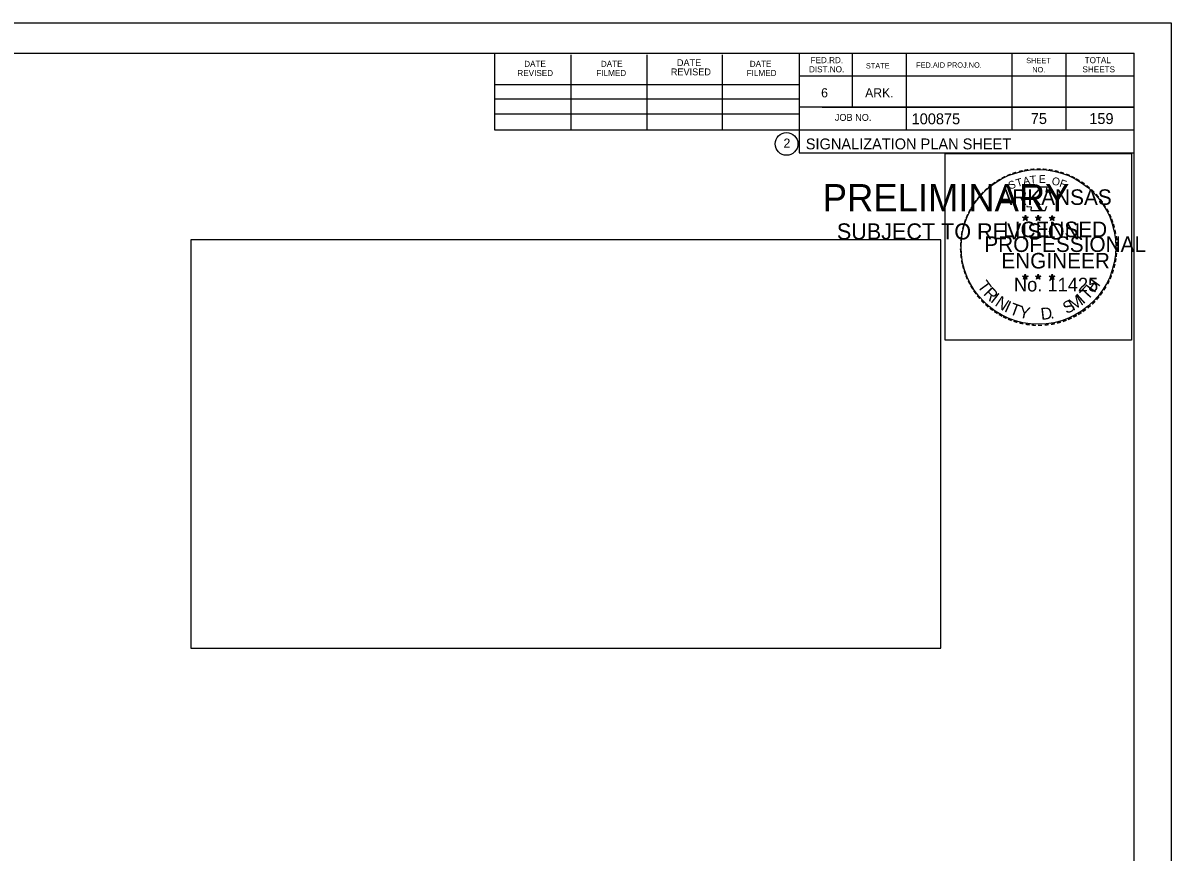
# Model space of a CAD drawing. Extents: x 1710114 to 1711114, y 557211 to 557851.
# Drawn here: x 1710671.2 to 1711114.3, y 557531.1 to 557851.1 of the extents above; entities that cross this region are included whole.
import ezdxf

# ---------------------------------------------------------------- set-up
doc = ezdxf.new("R2010")
doc.units = 0
for name, color, linetype in [('E_Existing ROW', 7, 'Continuous'), ('R_Alt Surface', 7, 'Continuous'), ('R_Alt Surface Annot', 7, 'Continuous'), ('R_Axis', 7, 'Continuous'), ('R_Axis Annot', 7, 'Continuous')]:
    doc.layers.add(name, color=color, linetype=linetype)

msp = doc.modelspace()

# ---------------------------------------------------------------- linework, layer by layer
at = {"layer": 'E_Existing ROW'}
msp.add_lwpolyline([(1710735.98, 557609.87), (1711025.48, 557609.87), (1711025.48, 557767.42), (1710735.98, 557767.42)], close=True, dxfattribs=at)
at = {"layer": 'R_Alt Surface'}
for p, q in [((1710151.54, 557839.47), (1711100.08, 557839.47)), ((1710853.3, 557809.83), (1710853.3, 557839.47)), ((1710882.88, 557809.83), (1710882.88, 557838.87)), ((1710912.16, 557809.83), (1710912.16, 557838.87)), ((1710941.2, 557809.83), (1710941.2, 557838.87)), ((1710970.78, 557839.47), (1710970.78, 557801.07)), ((1710991.3, 557839.47), (1710991.3, 557818.65)), ((1711012.12, 557839.47), (1711012.12, 557809.83)), ((1711052.86, 557839.47), (1711052.86, 557809.83)), ((1711073.68, 557839.47), (1711073.68, 557809.83)), ((1711100.08, 557223.09), (1711100.08, 557839.47)), ((1711100.08, 557830.65), (1710970.78, 557830.65)), ((1711100.08, 557830.71), (1711100.08, 557830.71)), ((1710853.3, 557827.41), (1710970.78, 557827.41)), ((1710853.3, 557821.83), (1710970.78, 557821.83)), ((1710853.3, 557809.83), (1710853.3, 557816.01)), ((1710853.3, 557816.01), (1710970.78, 557816.01)), ((1711100.08, 557818.65), (1710970.78, 557818.65)), ((1710979.66, 557818.65), (1711100.08, 557818.65)), ((1711100.08, 557809.83), (1710853.3, 557809.83)), ((1710970.78, 557801.07), (1711100.08, 557801.07))]:
    msp.add_line(p, q, dxfattribs=at)
msp.add_circle((1710965.94, 557804.47), 4.4, dxfattribs=at)
at = {"layer": 'R_Alt Surface Annot'}
for p, q in [((1710114.34, 557851.15), (1711114.34, 557851.15)), ((1711026.91, 557732.02), (1711026.91, 557732.02))]:
    msp.add_line(p, q, dxfattribs=at)
for points in [[(1710114.32, 557851.15), (1711114.34, 557851.15), (1711114.34, 557211.14), (1710114.32, 557211.14)], [(1711027.14, 557800.7), (1711099.14, 557800.7), (1711099.14, 557728.7), (1711027.14, 557728.7)]]:
    msp.add_lwpolyline(points, close=True, dxfattribs=at)
msp.add_circle((1711063.14, 557764.7), 29.86, dxfattribs=at)
at = {"layer": 'R_Axis Annot'}
for p, q in [((1711057.06, 557776.15), (1711058.11, 557775.81)), ((1711057.06, 557776.15), (1711057.82, 557776.01)), ((1711057.06, 557776.15), (1711057.77, 557775.78)), ((1711057.46, 557774.92), (1711058.11, 557775.81)), ((1711057.46, 557774.92), (1711057.84, 557775.66)), ((1711057.46, 557774.92), (1711058.1, 557775.57)), ((1711058.11, 557776.91), (1711057.99, 557776.15)), ((1711058.75, 557774.92), (1711058.1, 557775.57)), ((1711058.11, 557775.81), (1711058.11, 557776.91)), ((1711058.11, 557776.91), (1711058.26, 557776.16)), ((1711059.15, 557776.15), (1711058.11, 557775.81)), ((1711058.75, 557774.92), (1711058.11, 557775.81)), ((1711059.15, 557776.15), (1711058.29, 557776)), ((1711058.75, 557774.92), (1711058.34, 557775.8)), ((1711059.15, 557776.15), (1711058.54, 557775.84)), ((1711062.07, 557776.15), (1711063.12, 557775.81)), ((1711062.07, 557776.15), (1711062.83, 557776.01)), ((1711062.07, 557776.15), (1711062.78, 557775.78)), ((1711062.47, 557774.92), (1711063.12, 557775.81)), ((1711062.47, 557774.92), (1711062.85, 557775.66)), ((1711062.47, 557774.92), (1711063.11, 557775.57)), ((1711063.12, 557776.91), (1711063, 557776.15)), ((1711063.76, 557774.92), (1711063.11, 557775.57)), ((1711063.12, 557775.81), (1711063.12, 557776.91)), ((1711063.12, 557776.91), (1711063.27, 557776.16)), ((1711064.16, 557776.15), (1711063.12, 557775.81)), ((1711063.76, 557774.92), (1711063.12, 557775.81)), ((1711064.16, 557776.15), (1711063.3, 557776)), ((1711063.76, 557774.92), (1711063.35, 557775.8)), ((1711064.16, 557776.15), (1711063.55, 557775.84)), ((1711067.36, 557776.11), (1711068.41, 557775.78)), ((1711067.36, 557776.11), (1711068.12, 557775.98)), ((1711067.36, 557776.11), (1711068.08, 557775.75)), ((1711067.76, 557774.89), (1711068.41, 557775.78)), ((1711067.76, 557774.89), (1711068.14, 557775.62)), ((1711067.76, 557774.89), (1711068.41, 557775.54)), ((1711068.41, 557776.87), (1711068.29, 557776.12)), ((1711068.41, 557775.78), (1711068.41, 557776.87)), ((1711068.41, 557776.87), (1711068.56, 557776.12)), ((1711069.45, 557776.11), (1711068.41, 557775.78)), ((1711069.05, 557774.89), (1711068.41, 557775.78)), ((1711069.05, 557774.89), (1711068.41, 557775.53)), ((1711069.45, 557776.11), (1711068.59, 557775.96)), ((1711069.05, 557774.89), (1711068.64, 557775.76)), ((1711069.45, 557776.11), (1711068.84, 557775.81)), ((1711057.05, 557753.43), (1711058.1, 557753.1)), ((1711057.05, 557753.43), (1711057.81, 557753.29)), ((1711057.05, 557753.43), (1711057.76, 557753.06)), ((1711057.45, 557752.2), (1711058.1, 557753.1)), ((1711057.45, 557752.2), (1711057.83, 557752.94)), ((1711058.1, 557754.19), (1711057.97, 557753.43)), ((1711058.1, 557753.1), (1711058.1, 557754.19)), ((1711058.1, 557754.19), (1711058.24, 557753.44)), ((1711059.14, 557753.43), (1711058.1, 557753.1)), ((1711058.74, 557752.2), (1711058.1, 557753.1)), ((1711059.14, 557753.43), (1711058.28, 557753.28)), ((1711058.74, 557752.2), (1711058.33, 557753.08)), ((1711059.14, 557753.43), (1711058.53, 557753.12)), ((1711062.06, 557753.43), (1711063.1, 557753.1)), ((1711062.06, 557753.43), (1711062.82, 557753.29)), ((1711062.06, 557753.43), (1711062.77, 557753.06)), ((1711062.46, 557752.2), (1711063.1, 557753.1)), ((1711062.46, 557752.2), (1711062.83, 557752.94)), ((1711063.1, 557754.19), (1711062.98, 557753.43)), ((1711063.1, 557753.1), (1711063.1, 557754.19)), ((1711063.1, 557754.19), (1711063.25, 557753.44)), ((1711064.15, 557753.43), (1711063.1, 557753.1)), ((1711063.74, 557752.2), (1711063.1, 557753.1)), ((1711064.15, 557753.43), (1711063.29, 557753.28)), ((1711063.74, 557752.2), (1711063.33, 557753.08)), ((1711064.15, 557753.43), (1711063.53, 557753.12)), ((1711067.36, 557753.4), (1711068.41, 557753.07)), ((1711067.36, 557753.4), (1711068.12, 557753.26)), ((1711067.36, 557753.4), (1711068.07, 557753.03)), ((1711067.76, 557752.17), (1711068.41, 557753.07)), ((1711067.76, 557752.17), (1711068.14, 557752.91)), ((1711068.41, 557754.16), (1711068.28, 557753.4)), ((1711068.41, 557753.07), (1711068.41, 557754.16)), ((1711068.41, 557754.16), (1711068.55, 557753.41)), ((1711069.45, 557753.4), (1711068.41, 557753.07)), ((1711069.04, 557752.17), (1711068.41, 557753.07)), ((1711069.45, 557753.4), (1711068.59, 557753.25)), ((1711069.04, 557752.17), (1711068.63, 557753.05)), ((1711069.45, 557753.4), (1711068.83, 557753.09)), ((1711057.45, 557752.2), (1711058.09, 557752.86)), ((1711058.74, 557752.2), (1711058.09, 557752.85)), ((1711062.46, 557752.2), (1711063.1, 557752.86)), ((1711063.74, 557752.2), (1711063.1, 557752.85)), ((1711067.76, 557752.17), (1711068.4, 557752.83)), ((1711069.04, 557752.17), (1711068.4, 557752.82))]:
    msp.add_line(p, q, dxfattribs=at)
for points in [[(1711057.19, 557787.78), (1711057.99, 557785.3)], [(1711067.72, 557785.02), (1711068.14, 557785.87), (1711066.09, 557785.8), (1711066.53, 557787.78), (1711057.19, 557787.78)], [(1711058.66, 557780.51), (1711058.66, 557780.25), (1711060.35, 557780.19), (1711060.19, 557778.78), (1711065.8, 557778.78), (1711066.4, 557780.38)], [(1711058.11, 557776.91), (1711058.75, 557774.92), (1711057.06, 557776.15), (1711059.15, 557776.15), (1711057.46, 557774.92), (1711058.11, 557776.91)], [(1711063.12, 557776.91), (1711063.76, 557774.92), (1711062.07, 557776.15), (1711064.16, 557776.15), (1711062.47, 557774.92), (1711063.12, 557776.91)], [(1711068.41, 557776.87), (1711069.05, 557774.89), (1711067.36, 557776.11), (1711069.45, 557776.11), (1711067.76, 557774.89), (1711068.41, 557776.87)], [(1711058.1, 557754.19), (1711058.74, 557752.2), (1711057.05, 557753.43), (1711059.14, 557753.43), (1711057.45, 557752.2), (1711058.1, 557754.19)], [(1711063.1, 557754.19), (1711063.74, 557752.2), (1711062.06, 557753.43), (1711064.15, 557753.43), (1711062.46, 557752.2), (1711063.1, 557754.19)], [(1711068.41, 557754.16), (1711069.04, 557752.17), (1711067.36, 557753.4), (1711069.45, 557753.4), (1711067.76, 557752.17), (1711068.41, 557754.16)]]:
    msp.add_lwpolyline(points, dxfattribs=at)
for centre, radius in [((1711058.11, 557775.81), 0.517), ((1711058.11, 557775.81), 0.434), ((1711058.11, 557775.81), 0.347), ((1711058.11, 557775.81), 0.297), ((1711058.11, 557775.81), 0.224), ((1711058.11, 557775.81), 0.149), ((1711058.11, 557775.81), 0.0889), ((1711063.12, 557775.81), 0.517), ((1711063.12, 557775.81), 0.434), ((1711063.12, 557775.81), 0.347), ((1711063.12, 557775.81), 0.297), ((1711063.12, 557775.81), 0.224), ((1711063.12, 557775.81), 0.149), ((1711063.12, 557775.81), 0.0889), ((1711068.41, 557775.78), 0.517), ((1711068.41, 557775.78), 0.434), ((1711068.41, 557775.78), 0.347), ((1711068.41, 557775.78), 0.297), ((1711068.41, 557775.78), 0.224), ((1711068.41, 557775.78), 0.149), ((1711068.41, 557775.78), 0.0889), ((1711058.09, 557753.09), 0.517), ((1711058.09, 557753.09), 0.434), ((1711058.09, 557753.09), 0.347), ((1711058.09, 557753.09), 0.297), ((1711058.09, 557753.09), 0.224), ((1711058.09, 557753.09), 0.149), ((1711058.09, 557753.09), 0.0889), ((1711063.1, 557753.09), 0.517), ((1711063.1, 557753.09), 0.434), ((1711063.1, 557753.09), 0.347), ((1711063.1, 557753.09), 0.297), ((1711063.1, 557753.09), 0.224), ((1711063.1, 557753.09), 0.149), ((1711063.1, 557753.09), 0.0889), ((1711068.4, 557753.06), 0.517), ((1711068.4, 557753.06), 0.434), ((1711068.4, 557753.06), 0.347), ((1711068.4, 557753.06), 0.297), ((1711068.4, 557753.06), 0.224), ((1711068.4, 557753.06), 0.149), ((1711068.4, 557753.06), 0.0889)]:
    msp.add_circle(centre, radius, dxfattribs=at)

# ---------------------------------------------------------------- texts
at = {"layer": 'R_Alt Surface'}
for s, height, p in [('DATE', 2.638, (1710923.62, 557834.49)), ('FED.RD.', 2.346, (1710975.22, 557835.63)), ('SHEET', 2.052, (1711058.44, 557835.63)), ('TOTAL', 2.346, (1711081, 557835.63)), ('REVISED', 2.346, (1710862.06, 557830.65)), ('DATE', 2.346, (1710864.7, 557834.19)), ('FILMED', 2.346, (1710892.54, 557830.65)), ('DATE', 2.346, (1710894.28, 557834.19)), ('REVISED', 2.638, (1710921.28, 557830.95)), ('FILMED', 2.346, (1710950.56, 557830.65)), ('DATE', 2.346, (1710951.76, 557834.19)), ('DIST.NO.', 2.346, (1710974.62, 557832.09)), ('STATE', 2.052, (1710996.58, 557833.59)), ('FED.AID PROJ.NO.', 2.052, (1711015.96, 557833.89)), ('NO.', 2.052, (1711060.78, 557832.09)), ('SHEETS', 2.346, (1711080.16, 557832.09)), ('6', 3.52, (1710979.3, 557822.43)), ('ARK.', 3.517, (1710996.28, 557822.43)), ('JOB NO.', 2.638, (1710984.58, 557813.37)), ('100875', 4.2, (1711014.21, 557812.04)), ('75', 4.2, (1711060.2, 557812.14)), ('159', 4.2, (1711082.78, 557812.14)), ('2', 3.52, (1710964.79, 557803.01)), ('SIGNALIZATION PLAN SHEET', 4.2, (1710973.37, 557802.36))]:
    msp.add_text(s, height=height, dxfattribs=at).set_placement(p)
at = {"layer": 'R_Axis'}
for s, height, p in [('PRELIMINARY', 10.5, (1710979.93, 557778.46)), ('SUBJECT TO REVISION', 6.2253, (1710985.36, 557767.57))]:
    msp.add_text(s, height=height, dxfattribs=at).set_placement(p)
at = {"layer": 'R_Axis Annot'}
for s, height, rotation, p in [('-', 4.8, 24.3072, (1711051.53, 557790.36)), ('-', 4.8, 19.1761, (1711053.43, 557791.16)), ('-', 4.8, 13.6302, (1711055.68, 557791.89)), ('-', 4.8, 10.2193, (1711057.71, 557792.37)), ('-', 4.8, 5.8968, (1711059.9, 557792.7)), ('-', 4.8, 0.1862, (1711062.22, 557792.92)), ('-', 4.8, 357.743, (1711064.39, 557792.88)), ('-', 4.8, 352.1617, (1711066.62, 557792.71)), ('-', 4.8, 347.2049, (1711068.77, 557792.37)), ('-', 4.8, 342.3362, (1711070.68, 557791.9)), ('-', 4.8, 337.8551, (1711072.88, 557791.23)), ('-', 4.8, 38.9507, (1711044.68, 557785.98)), ('-', 4.8, 36.2317, (1711046.1, 557787.11)), ('-', 4.8, 34.0636, (1711047.84, 557788.29)), ('-', 4.8, 28.7918, (1711049.63, 557789.4)), ('S', 3, 21.594, (1711052.25, 557786.82)), ('T', 3, 16.4036, (1711054.99, 557787.81)), ('A', 3, 11.2132, (1711057.47, 557788.56)), ('T', 3, 6.0228, (1711060.02, 557789.06)), ('E', 3, 0.8323, (1711063.33, 557789.39)), ('O', 3, 350.4515, (1711068.14, 557788.76)), ('F', 3, 340.0707, (1711071.01, 557788.08)), ('-', 4.8, 334.1211, (1711074.78, 557790.42)), ('-', 4.8, 329.6409, (1711076.51, 557789.57)), ('-', 4.8, 325.8627, (1711078.44, 557788.49)), ('-', 4.8, 320.5297, (1711080.27, 557787.21)), ('-', 4.8, 50.6142, (1711040.82, 557781.83)), ('-', 4.8, 48.4231, (1711042.03, 557783.29)), ('-', 4.8, 42.9622, (1711043.38, 557784.72)), ('-', 4.8, 315.5786, (1711082.07, 557785.75)), ('-', 4.8, 309.8797, (1711083.78, 557784.1)), ('-', 4.8, 58.0706, (1711038.61, 557778.55)), ('-', 4.8, 54.2325, (1711039.58, 557780.13)), ('-', 4.8, 306.6522, (1711085.35, 557782.29)), ('-', 4.2, 303.6753, (1711086.81, 557780.59)), ('-', 4.8, 299.6684, (1711087.77, 557778.77)), ('-', 4.8, 72.3945, (1711036.24, 557772.99)), ('-', 4.8, 67.7743, (1711036.89, 557774.88)), ('-', 4.8, 62.8713, (1711037.67, 557776.71)), ('-', 4.8, 294.6628, (1711088.74, 557776.93)), ('-', 4.8, 290.5728, (1711089.51, 557775.2)), ('-', 4.8, 81.2013, (1711035.25, 557768.7)), ('-', 4.8, 75.461, (1711035.65, 557770.84)), ('-', 4.8, 285.1233, (1711090.21, 557773.46)), ('-', 4.8, 280.5493, (1711090.81, 557771.23)), ('-', 4.8, 89.0622, (1711034.95, 557764.53)), ('-', 4.8, 85.1863, (1711035.02, 557766.63)), ('-', 4.8, 276.5962, (1711091.3, 557768.93)), ('-', 4.8, 274.3301, (1711091.48, 557766.76)), ('-', 4.8, 94.1959, (1711035.05, 557762.35)), ('-', 4.8, 98.9479, (1711035.27, 557760.35)), ('-', 4.8, 263.5172, (1711091.52, 557762.87)), ('-', 4.8, 269.9407, (1711091.58, 557764.87)), ('-', 4.8, 101.7149, (1711035.67, 557758.15)), ('-', 4.8, 105.4578, (1711036.16, 557756.37)), ('-', 4.8, 255.7626, (1711090.98, 557758.87)), ('-', 4.8, 260.9953, (1711091.31, 557760.91)), ('-', 4.8, 109.0874, (1711036.8, 557754.48)), ('-', 4.8, 114.0643, (1711037.57, 557752.69)), ('-', 4.8, 247.8887, (1711089.77, 557754.69)), ('-', 4.8, 252.8681, (1711090.44, 557756.71)), ('-', 4.8, 115.7289, (1711038.48, 557750.83)), ('-', 4.8, 120.4471, (1711039.55, 557749.08)), ('T', 4.62, 306.0406, (1711039.38, 557749.61)), ('R', 4.62, 314.005, (1711041.66, 557746.47)), ('T', 4.62, 46.6444, (1711082.07, 557743.89)), ('H', 4.62, 54.6088, (1711084.74, 557746.72)), ('-', 4.8, 239.0712, (1711087.8, 557750.55)), ('-', 4.8, 244.6197, (1711088.98, 557752.81)), ('-', 4.8, 125.8934, (1711040.76, 557747.39)), ('-', 4.8, 130.7181, (1711042.15, 557745.74)), ('-', 4.8, 134.2238, (1711043.7, 557744.1)), ('I', 4.62, 321.9694, (1711044.37, 557743.67)), ('N', 4.62, 326.5002, (1711046.07, 557742.26)), ('S', 4.62, 26.9312, (1711074.01, 557738.7)), ('M', 4.62, 32.6563, (1711076.53, 557739.91)), ('I', 4.62, 42.1136, (1711080.38, 557742.45)), ('-', 4.8, 231.2538, (1711085.3, 557746.89)), ('-', 4.8, 233.8452, (1711086.59, 557748.59)), ('-', 4.8, 138.9338, (1711045.27, 557742.71)), ('-', 4.8, 144.6463, (1711046.94, 557741.49)), ('-', 4.8, 148.0898, (1711048.62, 557740.38)), ('I', 4.62, 335.3603, (1711049.69, 557739.9)), ('T', 4.62, 339.8912, (1711051.67, 557738.92)), ('Y', 4.62, 347.8556, (1711055.33, 557737.58)), ('D', 4.62, 6.3969, (1711064.28, 557736.5)), ('-', 4.8, 215.7363, (1711080.65, 557742.26)), ('-', 4.8, 221.0851, (1711082.3, 557743.68)), ('-', 4.8, 225.7653, (1711083.87, 557745.2)), ('-', 4.8, 151.5704, (1711050.36, 557739.4)), ('-', 4.8, 154.6002, (1711051.93, 557738.66)), ('-', 4.8, 158.5612, (1711053.8, 557737.9)), ('-', 4.8, 162.7983, (1711055.86, 557737.26)), ('-', 4.8, 167.5555, (1711058, 557736.77)), ('-', 4.8, 191.2858, (1711069.43, 557736.96)), ('.', 4.62, 13.7642, (1711067.86, 557736.89)), ('-', 4.8, 195.4743, (1711071.62, 557737.56)), ('-', 4.8, 200.7184, (1711073.65, 557738.28)), ('-', 4.8, 204.2516, (1711075.51, 557739.1)), ('-', 4.8, 207.3568, (1711077.38, 557740.06)), ('-', 4.8, 212.2491, (1711079.05, 557741.1)), ('-', 4.8, 173.1155, (1711060.32, 557736.44)), ('-', 4.8, 176.5183, (1711062.56, 557736.28)), ('-', 4.8, 181.5918, (1711064.8, 557736.34)), ('-', 4.8, 185.8167, (1711067.22, 557736.57))]:
    msp.add_text(s, height=height, rotation=rotation, dxfattribs=at).set_placement(p)
for s, height, p in [('ARKANSAS', 6, (1711047.74, 557780.92)), ('DWB', 0.03, (1711058.07, 557775.8)), ('DWB', 0.03, (1711063.08, 557775.8)), ('DWB', 0.03, (1711068.37, 557775.77)), ('LICENSED', 6, (1711049.54, 557768.47)), ('PROFESSIONAL', 6, (1711042.27, 557762.76)), ('ENGINEER', 6, (1711048.83, 557756.38)), ('DWB', 0.03, (1711058.06, 557753.08)), ('DWB', 0.03, (1711063.07, 557753.08)), ('DWB', 0.03, (1711068.37, 557753.05)), ('No. 11425', 5.271, (1711053.71, 557747.53))]:
    msp.add_text(s, height=height, dxfattribs=at).set_placement(p)

doc.saveas('drawing.dxf')
